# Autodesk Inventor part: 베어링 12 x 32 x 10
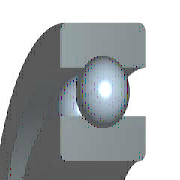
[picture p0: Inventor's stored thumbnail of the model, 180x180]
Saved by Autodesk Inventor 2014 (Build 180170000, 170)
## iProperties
IsCustomPart: 1
Created: 2012-02
Part Number: 베어링 12 x 32 x 10
Material: 강철, 연강
Description: 깊은 그루브 볼 베어링
Document SubType Name: Modeling
Standard: KS B 2023
Designer: test
Standards Organization: KS
Language: ko-KR
Size Designation: 6201 - 12 x 32 x 10
Categories: <MemberInstance><Categories><Category DisplayName="샤프트 부품" InternalName="7f7aeb1f-a693-4053-b835-cee3144e0d98" Mnemonic="SHFT"><Category DisplayName="베어링" Inter
Density: 1 g/cm^3
Appearance: 강철
Author: test
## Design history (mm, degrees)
sketch "스케치" dims "d0" = 5.2 (= -0.26 x WD + 0.26 x BD)
  geometry: L1 (2.4, 11)-(7.6, 11); L2 (5, 11)-(5, 8.4); L3 (5, 11)-(5, 13.6); L4 (3.068, 9.26)-(0, 9.26); L5 (0, 6)-(10, 6); L6 (3.068, 12.74)-(0, 12.74); L7 (0, 16)-(10, 16); L8 (10, 6)-(10, 9.26); L9 (6.932, 9.26)-(10, 9.26); L10 (6.932, 12.74)-(10, 12.74); L11 (10, 16)-(10, 12.74); L12 (-1.4, 0)-(8.4, 0) reference; L13 (0, -0.3)-(0, 5.3) reference
  constraints: 22 end point, 4 point on line, 2 collinear, 2 perpendicular, 2 symmetric about line, 1 midpoint, 1 parallel, 14 other
  dimensions: "d9" = 12 diameter of L5 L12 (= WD); "d11" = 32 diameter of L7 L12 (= BD); "d12" = 10 distance between parallel lines of L8 L13 (= KB); "d13" = 18.52 diameter of L9 L12 (= 0.326 x BD + 0.674 x WD)
revolve "본체" stored, may be unused: angle "d6" = 90 deg
revolve "볼" stored, may be unused: angle "d7" = 90 deg
pattern_circular "IDS_ARRAYBALL[SIMPL:T]" dims angle "d3" = 360 deg
body "Solid1"
fillet "모깎기1" dims "d1" = 0.6 (= KRS)
other parameters: "WD" = 12 [user parameter; used in 5 equation terms], "BD" = 32 [user parameter; used in 5 equation terms], "KB" = 10 [user parameter; used in 1 equation term], "KRS" = 0.6 [user parameter; used in 1 equation term], "d4" = 0, "d5" = 0, "d8" = 0, "d14" = 0, "d15" = 0, "BBA" = 0 [user parameter], "BC0" = 3100000 [user parameter], "BC" = 6890000 [user parameter], "BR" = 16 (= 0.5 x BD) [user parameter], "WR" = 6 (= 0.5 x WD) [user parameter]
